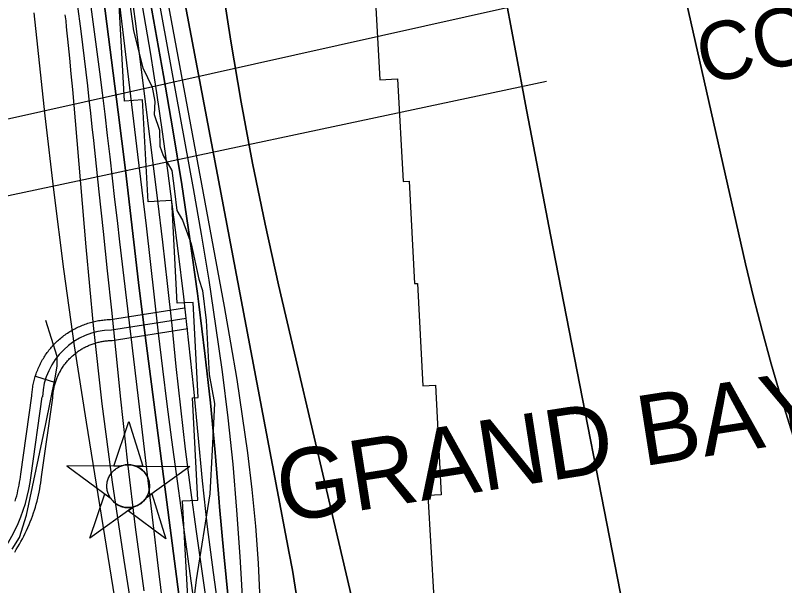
# Model space of a CAD drawing. Extents: x 3263578 to 3301413, y 764927 to 798602.
# Drawn here: x 3275974 to 3277071, y 790594 to 791406 of the extents above; entities that cross this region are included whole.
import ezdxf

# ---------------------------------------------------------------- set-up
doc = ezdxf.new("R2010")
doc.units = 0
for name, color, linetype in [('V-CHAN-NAID', 7, 'Continuous'), ('V-RIVR-EDGE', 7, 'Continuous'), ('V-RIVR-RANG', 7, 'Continuous'), ('V-ROAD-CNTR', 7, 'Continuous'), ('V-RRAP-RVMT', 7, 'Continuous'), ('V-TOPO-DPTH', 7, 'Continuous'), ('V-TOPO-MAJR', 7, 'Continuous'), ('V-TOPO-MINR', 7, 'Continuous'), ('V-TOPO-WATR', 7, 'Continuous'), ('V-UTIL-IDEN', 7, 'Continuous'), ('V-UTIL-LINE', 7, 'Continuous')]:
    doc.layers.add(name, color=color, linetype=linetype)

msp = doc.modelspace()

# ---------------------------------------------------------------- linework, layer by layer
at = {"layer": 'V-CHAN-NAID'}
for points in [[(3276124.2, 790763.7), (3276114.6, 790763.8), (3276135.8, 790827.3), (3276156, 790763.5), (3276146.4, 790763.5), (3276144.8, 790764.1), (3276142.7, 790764.7), (3276140.7, 790765.2), (3276138.6, 790765.5), (3276137.5, 790765.6), (3276135.9, 790765.7), (3276134.2, 790765.7), (3276132.9, 790765.6), (3276130.9, 790765.4), (3276129.6, 790765.2), (3276127.8, 790764.8), (3276126.3, 790764.4), (3276125.2, 790764.1)], [(3276124.2, 790763.7), (3276047.7, 790764.2), (3276109.3, 790718.8), (3276108.2, 790720.8), (3276107.4, 790722.4), (3276106.5, 790724.4), (3276105.8, 790726.4), (3276105.5, 790727.7), (3276105.1, 790729.4), (3276104.9, 790730.8), (3276104.7, 790732.4), (3276104.6, 790734.1), (3276104.6, 790735.7), (3276104.7, 790737.8), (3276104.9, 790739.4), (3276105.2, 790741.6), (3276105.7, 790743.5), (3276106.3, 790745.4), (3276107, 790747.1), (3276107.7, 790748.7), (3276108.5, 790750.2), (3276109.6, 790752), (3276110.6, 790753.4), (3276111.6, 790754.7), (3276112.6, 790755.8), (3276113.9, 790757.2), (3276115, 790758.1), (3276116.7, 790759.5), (3276117.9, 790760.4), (3276119.6, 790761.5), (3276121.3, 790762.4), (3276122.8, 790763.1)], [(3276146.4, 790763.5), (3276222.9, 790763), (3276160.7, 790718.5), (3276161.6, 790720), (3276162.6, 790721.8), (3276163.3, 790723.4), (3276164, 790725.4), (3276164.6, 790727.1), (3276165, 790728.8), (3276165.3, 790730.8), (3276165.5, 790732.4), (3276165.6, 790734.6), (3276165.6, 790736.6), (3276165.4, 790738.9), (3276165.2, 790740.6), (3276164.7, 790742.8), (3276164, 790745), (3276163.3, 790747), (3276162.6, 790748.4), (3276161.6, 790750.3), (3276160.6, 790752), (3276159.3, 790753.7), (3276158.1, 790755.3), (3276156.8, 790756.7), (3276155.2, 790758.2), (3276153.4, 790759.6), (3276151.8, 790760.8), (3276149.9, 790761.9), (3276148.4, 790762.7)], [(3276142.7, 790705.6), (3276080.4, 790661.1), (3276101.6, 790724.5), (3276109.3, 790718.8), (3276109.9, 790717.9), (3276111.3, 790716), (3276112.5, 790714.6), (3276114, 790713.1), (3276115.4, 790711.9), (3276116.8, 790710.7), (3276118.2, 790709.7), (3276119.9, 790708.7), (3276121.6, 790707.8), (3276123.4, 790707), (3276124.9, 790706.4), (3276126.5, 790705.9), (3276128.7, 790705.3), (3276130.2, 790705), (3276132.3, 790704.8), (3276133.8, 790704.7), (3276135.7, 790704.6), (3276137.4, 790704.7), (3276139.1, 790704.9), (3276141, 790705.2)], [(3276160.7, 790718.5), (3276168.5, 790724.1), (3276188.7, 790660.3), (3276134.9, 790700), (3276142.7, 790705.6), (3276144.3, 790706.1), (3276145.9, 790706.6), (3276148.1, 790707.5), (3276149.8, 790708.4), (3276151.7, 790709.5), (3276153.4, 790710.7), (3276155, 790712), (3276156.3, 790713.2), (3276157.6, 790714.6), (3276158.9, 790716), (3276160, 790717.4)]]:
    msp.add_lwpolyline(points, close=True, dxfattribs=at)
msp.add_circle((3276135.1, 790735.2), 30.5, dxfattribs=at)
at = {"layer": 'V-RIVR-EDGE'}
msp.add_lwpolyline([(3276126.7, 791497.5), (3276142.5, 791384.1), (3276155.9, 791331.4), (3276169.3, 791303.6), (3276173.1, 791283.1), (3276171.8, 791264.9), (3276179.6, 791242.3), (3276179.9, 791219.7), (3276184.7, 791206.2), (3276197.2, 791184.8), (3276201.1, 791155.3), (3276204.5, 791127.9), (3276212.3, 791114.4), (3276224.8, 791080.4), (3276235.5, 791030), (3276240.7, 791013.9), (3276246.3, 790971.3), (3276250.4, 790894.3), (3276258.1, 790853), (3276254.9, 790787), (3276251.3, 790724.4), (3276231.9, 790601.8), (3276226.5, 790558.4)], dxfattribs=at)
at = {"layer": 'V-RIVR-RANG'}
msp.add_line((3275889.9, 791133.7), (3276731.1, 791312.3), dxfattribs=at)
at = {"layer": 'V-ROAD-CNTR'}
msp.add_line((3276002.7, 790891.9), (3276031.2, 790882.8), dxfattribs=at)
for points in [[(3275977, 790725.3), (3275977.9, 790729.2), (3275978.7, 790733), (3275979.5, 790736.8), (3275980.2, 790740.7), (3275980.8, 790744.6), (3275981.3, 790748.4), (3275981.8, 790752.5), (3275997.6, 790864), (3275997.6, 790864), (3275997.8, 790866.1), (3275997.9, 790868), (3275998.1, 790870), (3275998.4, 790872), (3275998.6, 790874), (3275998.9, 790876), (3275999.3, 790878), (3275999.6, 790879.9), (3276000, 790881.9), (3276000.5, 790883.9), (3276001, 790885.8), (3276001.5, 790887.8), (3276002, 790889.7), (3276002.6, 790891.6), (3276003.2, 790893.6), (3276003.8, 790895.4), (3276004.5, 790897.3), (3276005.2, 790899.2), (3276006, 790901.1), (3276006.7, 790902.9), (3276007.6, 790904.8), (3276008.4, 790906.6), (3276009.3, 790908.4), (3276010.2, 790910.2), (3276011.1, 790912), (3276012.1, 790913.7), (3276013, 790915.5), (3276014.1, 790917.2), (3276015.1, 790919), (3276016.2, 790920.6), (3276017.3, 790922.3), (3276018.5, 790924), (3276019.6, 790925.6), (3276020.8, 790927.2), (3276022.1, 790928.8), (3276023.3, 790930.4), (3276024.6, 790931.9), (3276025.9, 790933.4), (3276027.2, 790934.9), (3276028.6, 790936.4), (3276030, 790937.9), (3276031.4, 790939.3), (3276032.9, 790940.7), (3276034.3, 790942.1), (3276035.8, 790943.4), (3276037.3, 790944.7), (3276038.8, 790946), (3276040.4, 790947.3), (3276042, 790948.6), (3276043.5, 790949.8), (3276045.2, 790951), (3276046.8, 790952.1), (3276048.5, 790953.3), (3276050.2, 790954.4), (3276051.9, 790955.5), (3276053.6, 790956.5), (3276055.3, 790957.5), (3276057.1, 790958.5), (3276058.8, 790959.4), (3276060.6, 790960.4), (3276062.4, 790961.2), (3276064.2, 790962.1), (3276066.1, 790962.9), (3276067.9, 790963.7), (3276069.8, 790964.5), (3276071.7, 790965.2), (3276073.5, 790965.9), (3276075.4, 790966.6), (3276077.3, 790967.2), (3276079.3, 790967.8), (3276081.2, 790968.4), (3276083.1, 790968.9), (3276085, 790969.4), (3276087, 790969.9), (3276089, 790970.3), (3276090.9, 790970.7), (3276092.9, 790971.1), (3276094.9, 790971.4), (3276096.9, 790971.7), (3276098.9, 790971.9), (3276100.8, 790972.1), (3276102.9, 790972.3), (3276104.9, 790972.5), (3276106.9, 790972.6), (3276108.9, 790972.7), (3276109.8, 790972.7), (3276215.5, 790989.3)], [(3275969.5, 790645.3), (3275979.9, 790662), (3275990.1, 790693.9), (3276017.7, 790823.8), (3276031, 790889.5), (3276034, 790906.3), (3276034, 790919.8), (3276017.8, 790971.3)], [(3276111.1, 790957.7), (3276217.8, 790974.5)], [(3276006.2, 790718.3), (3276007.2, 790722.6), (3276008.1, 790726.9), (3276009, 790731.3), (3276009.7, 790735.7), (3276010.4, 790740), (3276011.1, 790744.4), (3276011.6, 790748.6), (3276027.5, 790861.2), (3276027.6, 790862.4), (3276027.7, 790863.8), (3276027.8, 790865.3), (3276027.9, 790866.8), (3276028.1, 790868.3), (3276028.3, 790869.7), (3276028.5, 790871.2), (3276028.8, 790872.7), (3276029.1, 790874.2), (3276029.4, 790875.6), (3276029.7, 790877), (3276030.1, 790878.5), (3276030.4, 790879.9), (3276030.8, 790881.4), (3276031.2, 790882.8), (3276031.7, 790884.2), (3276032.2, 790885.6), (3276032.7, 790887), (3276033.2, 790888.4), (3276033.8, 790889.8), (3276034.3, 790891.1), (3276034.9, 790892.5), (3276035.5, 790893.8), (3276036.2, 790895.2), (3276036.8, 790896.5), (3276037.5, 790897.8), (3276038.3, 790899.1), (3276039, 790900.4), (3276039.7, 790901.7), (3276040.5, 790902.9), (3276041.3, 790904.2), (3276042.2, 790905.5), (3276043, 790906.6), (3276043.9, 790907.9), (3276044.8, 790909.1), (3276045.6, 790910.2), (3276046.6, 790911.4), (3276047.5, 790912.5), (3276048.5, 790913.7), (3276049.5, 790914.8), (3276050.5, 790915.9), (3276051.5, 790916.9), (3276052.6, 790918), (3276053.6, 790919), (3276054.7, 790920), (3276055.8, 790921.1), (3276056.9, 790922), (3276058.1, 790923), (3276059.2, 790923.9), (3276060.4, 790924.9), (3276061.6, 790925.8), (3276062.7, 790926.6), (3276063.9, 790927.5), (3276065.2, 790928.4), (3276066.4, 790929.2), (3276067.7, 790929.9), (3276068.9, 790930.7), (3276070.3, 790931.5), (3276071.5, 790932.2), (3276072.8, 790932.9), (3276074.1, 790933.6), (3276075.5, 790934.2), (3276076.8, 790934.9), (3276078.2, 790935.5), (3276079.6, 790936.1), (3276080.9, 790936.6), (3276082.3, 790937.2), (3276083.7, 790937.7), (3276085.1, 790938.2), (3276086.5, 790938.7), (3276087.9, 790939.1), (3276089.3, 790939.5), (3276090.8, 790939.9), (3276092.2, 790940.3), (3276093.6, 790940.6), (3276095.1, 790940.9), (3276096.6, 790941.2), (3276098.1, 790941.5), (3276099.5, 790941.7), (3276100.9, 790942), (3276102.4, 790942.1), (3276103.9, 790942.3), (3276105.4, 790942.4), (3276106.9, 790942.6), (3276108.4, 790942.6), (3276109.8, 790942.7), (3276112.4, 790942.8), (3276220.2, 790959.6)], [(3275996.7, 790750.6), (3276012.6, 790862.6)], [(3275973.9, 790714), (3275975, 790717.8), (3275976.1, 790721.6), (3275977, 790725.3)], [(3275973.2, 790641.1), (3275975.5, 790644.8), (3275977.8, 790648.6), (3275980, 790652.5), (3275982.2, 790656.3), (3275984.3, 790660.3), (3275986.3, 790664.2), (3275988.3, 790668.2), (3275990.2, 790672.2), (3275992, 790676.3), (3275993.7, 790680.4), (3275995.4, 790684.5), (3275997, 790688.6), (3275998.5, 790692.7), (3276000, 790697), (3276001.4, 790701.2), (3276002.7, 790705.4), (3276003.9, 790709.7), (3276005.1, 790713.9), (3276006.2, 790718.3)]]:
    msp.add_lwpolyline(points, dxfattribs=at)
for centre, radius, start, end in [((3276112.6, 790857.6), 100.1, 90.824, 177.135), ((3275759, 790778.3), 239.3, 314.4339, 353.3591)]:
    msp.add_arc(centre, radius, start, end, dxfattribs=at)
at = {"layer": 'V-RRAP-RVMT'}
for points in [[(3276485.7, 791460.2), (3276493.8, 791314.1), (3276518.9, 791315.5), (3276526.8, 791169.2), (3276535.6, 791169.6), (3276543.1, 791023.9), (3276547.4, 791024.1), (3276555.1, 790878.2), (3276572.9, 790879.1), (3276581, 790723.1), (3276562.3, 790722.1), (3276570.5, 790575.8), (3276566.1, 790575.6), (3276573.6, 790451.6), (3276574.6, 790451.7), (3276591.1, 790297.8), (3276581.9, 790296.8), (3276603.7, 790160.3), (3276589.3, 790158), (3276610.1, 790026.4), (3276618.1, 790027.7), (3276642.8, 789874.4), (3276641.3, 789874.1), (3276663.8, 789740.2)], [(3276363.8, 789681.5), (3276337.9, 789835.6), (3276341.7, 789836.2), (3276320.1, 789970), (3276307.6, 789968), (3276285.3, 790109.4), (3276284.4, 790109.2), (3276259.9, 790262.2), (3276251.5, 790261.2), (3276235.2, 790412.7), (3276223.5, 790412.1), (3276214, 790568.2), (3276220.4, 790568.6), (3276212.3, 790714.2), (3276234.3, 790715.3), (3276226.9, 790861.1), (3276234.9, 790861.6), (3276227.6, 790997), (3276204.6, 790995.8), (3276197, 791142), (3276163.4, 791140.2), (3276155.3, 791285.4), (3276129.9, 791283.9), (3276121.8, 791429.9)]]:
    msp.add_lwpolyline(points, dxfattribs=at)
at = {"layer": 'V-TOPO-DPTH'}
for points in [[(3276877.9, 791657.8), (3277015.2, 791052), (3277026.5, 791004.3), (3277038.6, 790956.8), (3277051.7, 790909.5), (3277065.5, 790862.5), (3277080.2, 790815.7), (3277095.5, 790769.1), (3277111.8, 790722.9), (3277128.6, 790676.8), (3277160.2, 790592.6), (3277170.8, 790562.6), (3277180.5, 790532.4), (3277188.8, 790501.8), (3277196.3, 790470.9), (3277222.7, 790351), (3277243.2, 790260.1), (3277264.4, 790169.3), (3277286.5, 790078.8), (3277309.3, 789988.4), (3277453.1, 789431.5)], [(3276877.9, 791657.8), (3277015.2, 791052), (3277026.5, 791004.3), (3277038.6, 790956.8), (3277051.7, 790909.5), (3277065.5, 790862.5), (3277080.2, 790815.7), (3277095.5, 790769.1), (3277111.8, 790722.9), (3277128.6, 790676.8), (3277160.2, 790592.6), (3277170.8, 790562.6), (3277180.5, 790532.4), (3277188.8, 790501.8), (3277196.3, 790470.9), (3277222.7, 790351), (3277243.2, 790260.1), (3277264.4, 790169.3), (3277286.5, 790078.8), (3277309.3, 789988.4), (3277453.1, 789431.5)], [(3276509.8, 789777.1), (3276505.2, 789809.9), (3276501.8, 789842.9), (3276499.2, 789875.9), (3276497.5, 789906.9), (3276496.6, 789924.6), (3276496, 789942.2), (3276418.7, 790298.4), (3276414.4, 790315.6), (3276410.6, 790332.9), (3276407.4, 790350.3), (3276404.6, 790367.8), (3276394.1, 790445.6), (3276390.7, 790469.9), (3276387.4, 790494.2), (3276384, 790518.5), (3276380.6, 790542.8), (3276377, 790567.1), (3276373.2, 790591.4), (3276369.1, 790615.5), (3276364.7, 790639.7), (3276199.1, 791512.6)], [(3276509.8, 789777.1), (3276505.2, 789809.9), (3276501.8, 789842.9), (3276499.2, 789875.9), (3276497.5, 789906.9), (3276496.6, 789924.6), (3276496, 789942.2), (3276418.7, 790298.4), (3276414.4, 790315.6), (3276410.6, 790332.9), (3276407.4, 790350.3), (3276404.6, 790367.8), (3276394.1, 790445.6), (3276390.7, 790469.9), (3276387.4, 790494.2), (3276384, 790518.5), (3276380.6, 790542.8), (3276377, 790567.1), (3276373.2, 790591.4), (3276369.1, 790615.5), (3276364.7, 790639.7), (3276199.1, 791512.6)], [(3276180.6, 791483.4), (3276271.8, 790991.2), (3276281, 790939.3), (3276289.7, 790887.2), (3276297.7, 790835.1), (3276305.2, 790782.9), (3276311.4, 790730.5), (3276316.7, 790678), (3276320.3, 790625.5), (3276322.9, 790572.8), (3276328.4, 790412.7), (3276329.3, 790395.3), (3276330.7, 790377.8), (3276332.8, 790360.5), (3276335.3, 790343.1), (3276339.7, 790316.1), (3276340.4, 790312.3), (3276341.1, 790308.6), (3276341.9, 790304.8), (3276342.7, 790301.1), (3276432.5, 789905.5), (3276450.9, 789820.7), (3276468.4, 789735.7)], [(3276180.6, 791483.4), (3276271.8, 790991.2), (3276281, 790939.3), (3276289.7, 790887.2), (3276297.7, 790835.1), (3276305.2, 790782.9), (3276311.4, 790730.5), (3276316.7, 790678), (3276320.3, 790625.5), (3276322.9, 790572.8), (3276328.4, 790412.7), (3276329.3, 790395.3), (3276330.7, 790377.8), (3276332.8, 790360.5), (3276335.3, 790343.1), (3276339.7, 790316.1), (3276340.4, 790312.3), (3276341.1, 790308.6), (3276341.9, 790304.8), (3276342.7, 790301.1), (3276432.5, 789905.5), (3276450.9, 789820.7), (3276468.4, 789735.7)], [(3276263.1, 791486.1), (3276281.5, 791369.4), (3276296.2, 791282.2), (3276312.2, 791195.2), (3276330.2, 791108.6), (3276349.4, 791022.2), (3276496.8, 790393.4), (3276501.1, 790375.8), (3276505.8, 790358.2), (3276510.8, 790340.7), (3276516.2, 790323.3), (3276667.7, 789275), (3276666.8, 789262.8), (3276668.7, 789249.3), (3276671, 789235.9), (3276673.8, 789222.6), (3276677, 789209.3), (3276697.6, 789130.3), (3276699.7, 789123), (3276702.1, 789115.7), (3276704.9, 789108.6), (3276708, 789101.5), (3277018.3, 788026.6)], [(3277018.3, 788026.6), (3276708, 789101.5), (3276704.9, 789108.6), (3276702.1, 789115.7), (3276699.7, 789123), (3276697.6, 789130.3), (3276677, 789209.3), (3276673.8, 789222.6), (3276671, 789235.9), (3276668.7, 789249.3), (3276666.8, 789262.8), (3276667.7, 789275), (3276516.2, 790323.3), (3276510.8, 790340.7), (3276505.8, 790358.2), (3276501.1, 790375.8), (3276496.8, 790393.4), (3276349.4, 791022.2), (3276330.2, 791108.6), (3276312.2, 791195.2), (3276296.2, 791282.2), (3276281.5, 791369.4), (3276263.1, 791486.1)], [(3276278.2, 790571.4), (3276271.3, 790638.6), (3276265.4, 790705.9), (3276264.9, 790712.5), (3276259, 790783.2), (3276252.2, 790853.8), (3276244.4, 790924.3), (3276235.7, 790994.7), (3276233.7, 791009.7), (3276223, 791087.5), (3276211.4, 791165.2), (3276198.8, 791242.7), (3276185.5, 791320.1), (3276161.5, 791453.7)], [(3276278.2, 790571.4), (3276271.3, 790638.6), (3276265.4, 790705.9), (3276264.9, 790712.5), (3276259, 790783.2), (3276252.2, 790853.8), (3276244.4, 790924.3), (3276235.7, 790994.7), (3276233.7, 791009.7), (3276223, 791087.5), (3276211.4, 791165.2), (3276198.8, 791242.7), (3276185.5, 791320.1), (3276161.5, 791453.7)], [(3277007.7, 789277.1), (3276935.5, 789903.1), (3276939, 789911.3), (3276917.3, 790125.8), (3276913.9, 790153.3), (3276910.3, 790180.8), (3276906.2, 790208.2), (3276901.8, 790235.6), (3276897, 790262.9), (3276892.2, 790290.3), (3276887.3, 790317.5), (3276882.2, 790344.8), (3276867.5, 790422.5), (3276864.5, 790438.7), (3276861.4, 790454.8), (3276858.3, 790471), (3276855.1, 790487.1), (3276737, 791093.5), (3276719.8, 791182.5), (3276702.8, 791271.5), (3276686.2, 791360.5), (3276669.7, 791449.6)], [(3276669.7, 791449.6), (3276686.2, 791360.5), (3276702.8, 791271.5), (3276719.8, 791182.5), (3276737, 791093.5), (3276855.1, 790487.1), (3276858.3, 790471), (3276861.4, 790454.8), (3276864.5, 790438.7), (3276867.5, 790422.5), (3276882.2, 790344.8), (3276887.3, 790317.5), (3276892.2, 790290.3), (3276897, 790262.9), (3276901.8, 790235.6), (3276906.2, 790208.2), (3276910.3, 790180.8), (3276913.9, 790153.3), (3276917.3, 790125.8), (3276939, 789911.3), (3276935.5, 789903.1), (3277007.7, 789277.1)], [(3276230.4, 790401.9), (3276160.5, 790938.8), (3276155.3, 790979.9), (3276150.2, 791021), (3276145.3, 791062.2), (3276140.6, 791103.3), (3276135.9, 791144.5), (3276131, 791185.6), (3276126, 791226.7), (3276120.8, 791267.9), (3276099.9, 791431.5)], [(3276142, 791418.1), (3276145.3, 791394.5), (3276148.4, 791370.8), (3276176.8, 791141.5), (3276183.8, 791082.6), (3276190.6, 791023.8), (3276197, 790964.8), (3276203.1, 790905.9), (3276209.4, 790847), (3276216.2, 790788.1), (3276223.8, 790729.3), (3276231.8, 790670.6), (3276276.1, 790361.4)], [(3276142, 791418.1), (3276145.3, 791394.5), (3276148.4, 791370.8), (3276176.8, 791141.5), (3276183.8, 791082.6), (3276190.6, 791023.8), (3276197, 790964.8), (3276203.1, 790905.9), (3276209.4, 790847), (3276216.2, 790788.1), (3276223.8, 790729.3), (3276231.8, 790670.6), (3276276.1, 790361.4)]]:
    msp.add_lwpolyline(points, dxfattribs=at)
at = {"layer": 'V-TOPO-MAJR'}
msp.add_lwpolyline([(3276044.9, 791406.9), (3276045.9, 791398.2), (3276046.8, 791389.5), (3276047.7, 791380.8), (3276048.6, 791372.2), (3276051.2, 791344.9), (3276053.4, 791322.6), (3276055.4, 791300.3), (3276057.4, 791278), (3276059.3, 791255.7), (3276074.5, 791076.1), (3276085.2, 790964.2), (3276097.5, 790852.5), (3276112.2, 790741), (3276128.6, 790629.8), (3276174.4, 790340.1)], dxfattribs=at)
at = {"layer": 'V-TOPO-MINR'}
for points in [[(3277453.1, 789431.5), (3277309.3, 789988.4), (3277286.5, 790078.8), (3277264.4, 790169.3), (3277243.2, 790260.1), (3277222.7, 790351), (3277196.3, 790470.9), (3277188.8, 790501.8), (3277180.5, 790532.4), (3277170.8, 790562.6), (3277160.2, 790592.6), (3277128.6, 790676.8), (3277111.8, 790722.9), (3277095.5, 790769.1), (3277080.2, 790815.7), (3277065.5, 790862.5), (3277051.7, 790909.5), (3277038.6, 790956.8), (3277026.5, 791004.3), (3277015.2, 791052), (3276877.9, 791657.8)], [(3276199.1, 791512.6), (3276364.7, 790639.7), (3276369.1, 790615.5), (3276373.2, 790591.4), (3276377, 790567.1), (3276380.6, 790542.8), (3276384, 790518.5), (3276387.4, 790494.2), (3276390.7, 790469.9), (3276394.1, 790445.6), (3276404.6, 790367.8), (3276407.4, 790350.3), (3276410.6, 790332.9), (3276414.4, 790315.6), (3276418.7, 790298.4), (3276496, 789942.2), (3276496.6, 789924.6), (3276497.5, 789906.9), (3276499.2, 789875.9), (3276501.8, 789842.9), (3276505.2, 789809.9), (3276509.8, 789777.1)], [(3276142, 791493.9), (3276157.5, 791405.6), (3276166.8, 791350.5), (3276175.6, 791295.4), (3276183.6, 791240.1), (3276191.1, 791184.8), (3276205.7, 791070.3), (3276213.7, 791004.9), (3276221.2, 790939.5), (3276228, 790874), (3276234.2, 790808.4), (3276240.6, 790742.9), (3276247.8, 790677.4), (3276256.2, 790612.1), (3276265.3, 790546.9)], [(3276180.6, 791483.4), (3276271.8, 790991.2), (3276281, 790939.3), (3276289.7, 790887.2), (3276297.7, 790835.1), (3276305.2, 790782.9), (3276311.4, 790730.5), (3276316.7, 790678), (3276320.3, 790625.5), (3276322.9, 790572.8), (3276328.4, 790412.7), (3276329.3, 790395.3), (3276330.7, 790377.8), (3276332.8, 790360.5), (3276335.3, 790343.1), (3276339.7, 790316.1), (3276340.4, 790312.3), (3276341.1, 790308.6), (3276341.9, 790304.8), (3276342.7, 790301.1), (3276432.5, 789905.5), (3276450.9, 789820.7), (3276468.4, 789735.7)], [(3276263.1, 791486.1), (3276281.5, 791369.4), (3276296.2, 791282.2), (3276312.2, 791195.2), (3276330.2, 791108.6), (3276349.4, 791022.2), (3276496.8, 790393.4), (3276501.1, 790375.8), (3276505.8, 790358.2), (3276510.8, 790340.7), (3276516.2, 790323.3), (3276667.7, 789275), (3276666.8, 789262.8), (3276668.7, 789249.3), (3276671, 789235.9), (3276673.8, 789222.6), (3276677, 789209.3), (3276697.6, 789130.3), (3276699.7, 789123), (3276702.1, 789115.7), (3276704.9, 789108.6), (3276708, 789101.5), (3277018.3, 788026.6)], [(3276056.9, 791461.7), (3276067.3, 791383.6), (3276069.8, 791364.1), (3276072.2, 791344.7), (3276074.6, 791325.2), (3276076.8, 791305.7), (3276079, 791286.2), (3276081.2, 791266.7), (3276083.3, 791247.2), (3276085.4, 791227.6), (3276093.3, 791154.4), (3276099.3, 791098.2), (3276105.2, 791042), (3276111, 790985.9), (3276116.7, 790929.7), (3276123.9, 790859.3), (3276133.9, 790768), (3276144.9, 790676.9), (3276157.4, 790585.9)], [(3276171.1, 791468.6), (3276227.6, 791159.2), (3276239.1, 791094.1), (3276249.9, 791028.8), (3276259.7, 790963.5), (3276268.9, 790898), (3276277, 790832.4), (3276284, 790766.7), (3276289.5, 790700.8), (3276294.1, 790634.9), (3276298.8, 790553.8), (3276301.8, 790512.3), (3276305.7, 790471), (3276310.8, 790429.7), (3276316.7, 790388.5), (3276326.9, 790325.1), (3276328.5, 790315.7), (3276330.1, 790306.4), (3276332, 790297.1), (3276333.9, 790287.8), (3276401.5, 789976.4), (3276416.7, 789904), (3276431.2, 789831.5), (3276444.7, 789758.7)], [(3276118.2, 791457.7), (3276148.5, 791207.8), (3276154.5, 791157), (3276160.5, 791106.1), (3276166.2, 791055.2), (3276171.9, 791004.3), (3276177.6, 790953.4), (3276183.7, 790902.6), (3276190.1, 790851.8), (3276196.9, 790801), (3276261.1, 790334)], [(3276161.5, 791453.7), (3276185.5, 791320.1), (3276198.8, 791242.7), (3276211.4, 791165.2), (3276223, 791087.5), (3276233.7, 791009.7), (3276235.7, 790994.7), (3276244.4, 790924.3), (3276252.2, 790853.8), (3276259, 790783.2), (3276264.9, 790712.5), (3276265.4, 790705.9), (3276271.3, 790638.6), (3276278.2, 790571.4)], [(3277007.7, 789277.1), (3276935.5, 789903.1), (3276939, 789911.3), (3276917.3, 790125.8), (3276913.9, 790153.3), (3276910.3, 790180.8), (3276906.2, 790208.2), (3276901.8, 790235.6), (3276897, 790262.9), (3276892.2, 790290.3), (3276887.3, 790317.5), (3276882.2, 790344.8), (3276867.5, 790422.5), (3276864.5, 790438.7), (3276861.4, 790454.8), (3276858.3, 790471), (3276855.1, 790487.1), (3276737, 791093.5), (3276719.8, 791182.5), (3276702.8, 791271.5), (3276686.2, 791360.5), (3276669.7, 791449.6)], [(3276078, 791446.9), (3276093.9, 791325.7), (3276097.8, 791295.4), (3276101.6, 791265.1), (3276105.2, 791234.8), (3276108.7, 791204.5), (3276112.2, 791174.2), (3276115.6, 791143.8), (3276119.2, 791113.5), (3276122.7, 791083.2), (3276148.6, 790864.4), (3276155.8, 790803.9), (3276162.9, 790743.3), (3276170.1, 790682.8), (3276177.2, 790622.2), (3276178.6, 790610.3), (3276185.3, 790555.7)], [(3276099.9, 791431.5), (3276120.8, 791267.9), (3276126, 791226.7), (3276131, 791185.6), (3276135.9, 791144.5), (3276140.6, 791103.3), (3276145.3, 791062.2), (3276150.2, 791021), (3276155.3, 790979.9), (3276160.5, 790938.8), (3276230.4, 790401.9)], [(3276000.3, 791409.7), (3276016.2, 791262.8), (3276028.8, 791153.4), (3276042.7, 791044.2), (3276058.2, 790935.2), (3276075, 790826.4), (3276160.3, 790299.2), (3276162.8, 790283.7), (3276165.5, 790268.3), (3276168.2, 790252.8), (3276171.1, 790237.4), (3276174.6, 790218.4), (3276175.6, 790212.4), (3276176.6, 790206.5), (3276177.3, 790200.5), (3276178, 790194.5), (3276178.3, 790188.5), (3276178.2, 790182.5), (3276375.2, 789020.5)]]:
    msp.add_lwpolyline(points, dxfattribs=at)
at = {"layer": 'V-TOPO-WATR'}
msp.add_lwpolyline([(3276142, 791418.1), (3276145.3, 791394.5), (3276148.4, 791370.8), (3276176.8, 791141.5), (3276183.8, 791082.6), (3276190.6, 791023.8), (3276197, 790964.8), (3276203.1, 790905.9), (3276209.4, 790847), (3276216.2, 790788.1), (3276223.8, 790729.3), (3276231.8, 790670.6), (3276276.1, 790361.4)], dxfattribs=at)
at = {"layer": 'V-UTIL-LINE'}
msp.add_line((3274912.9, 791023.7), (3281090.3, 792403.8), dxfattribs=at)

# ---------------------------------------------------------------- texts
at = {"layer": 'V-CHAN-NAID'}
msp.add_text('GRAND BAY (258.8)', height=100, rotation=8.8807, dxfattribs=at).set_placement((3276354.9, 790683.1))
at = {"layer": 'V-UTIL-IDEN'}
msp.add_text('COLONIAL PIPELINE CO.', height=83, rotation=12.8907, dxfattribs=at).set_placement((3276956.1, 791306.9))

doc.saveas('drawing.dxf')
